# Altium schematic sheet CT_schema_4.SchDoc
size 293 x 134 mm
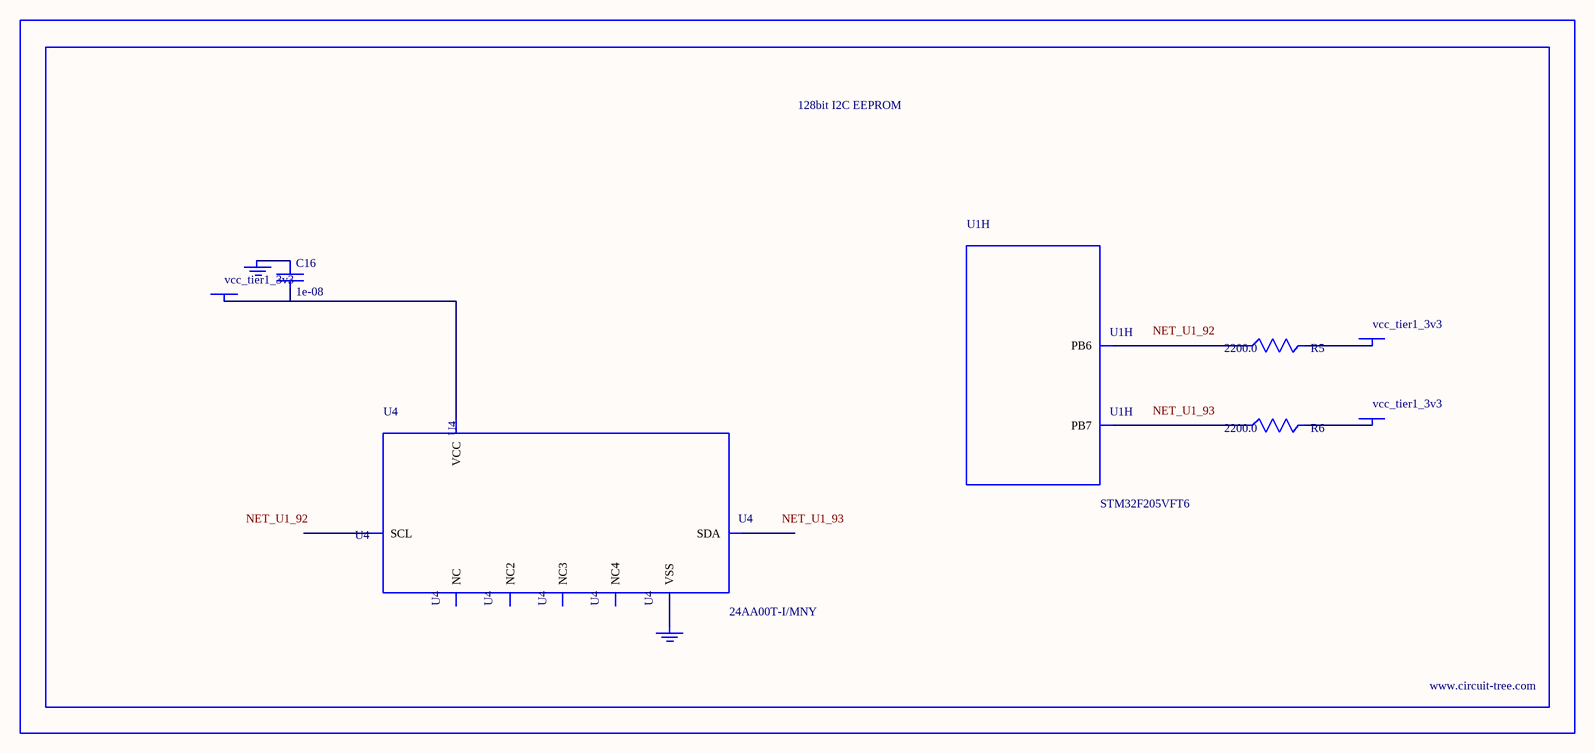
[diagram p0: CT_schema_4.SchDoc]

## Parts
BORDER3  (no value)
C16  1e-08  [C0402]
GND_INSTANCE_3_0  (no value)
GND_INSTANCE_3_1  (no value)
POWER_INSTANCE_3_0  vcc_tier1_3v3
POWER_INSTANCE_3_1  vcc_tier1_3v3
POWER_INSTANCE_3_2  vcc_tier1_3v3
R5  2200.0  [R0603]
R6  2200.0  [R0603]
U1  STM32F205VFT6  [LQFP100]  (part H of 11)
U4  24AA00T-I/MNY  [TDFN-8/6MM]

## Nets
NetC16_1: C16.1 GND_INSTANCE_3_0.0(GND)
NetC16_2: C16.2 POWER_INSTANCE_3_0.0(PWR) U4.8(VCC)
NetGND_INSTANCE_3_1_0: GND_INSTANCE_3_1.0(GND) U4.4(VSS)
NetPOWER_INSTANCE_3_1_0: POWER_INSTANCE_3_1.0(PWR) R5.2
NetPOWER_INSTANCE_3_2_0: POWER_INSTANCE_3_2.0(PWR) R6.2
NetR5_1: R5.1 U1.92(PB6)
NetR6_1: R6.1 U1.93(PB7)

Not connected (* = marked no-connect by the designer): U4 1(NC) 2(NC2) 3(NC3) 5(SDA) 6(SCL) 7(NC4)

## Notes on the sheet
- Labels drawn without touching a wire or pin: NET_U1_92, NET_U1_93

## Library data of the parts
BORDER3 = BORDER_PAGE3
C16 = C0402C103K3RAC
GND_INSTANCE_3_0 GND_INSTANCE_3_1 = GND
POWER_INSTANCE_3_0-POWER_INSTANCE_3_2 = PWR
R5 R6 = RC0603JR-072K2L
